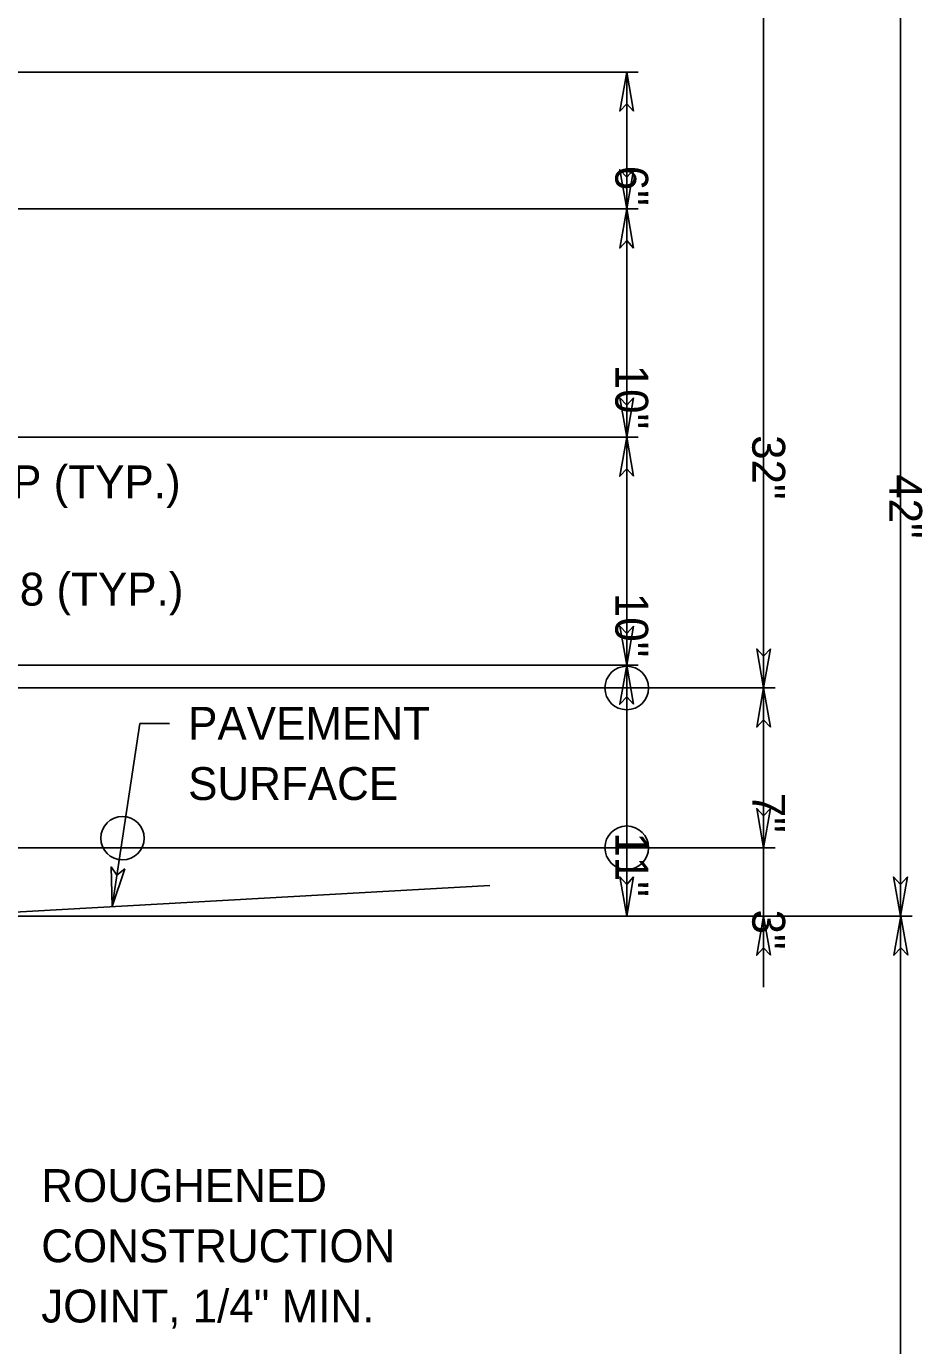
# Model space of a CAD drawing. Extents: x -26.5 to -19.2, y -3.6 to 6.6.
# Drawn here: x -22.083 to -20.447, y 2.961 to 5.371 of the extents above; entities that cross this region are included whole.
import ezdxf

# ---------------------------------------------------------------- set-up
doc = ezdxf.new("R2010")
doc.units = 0
for name, color, linetype in [('ANNO-WOUT', 7, 'Continuous'), ('DETL-DIMS', 7, 'Continuous'), ('Level 10', 7, 'Continuous'), ('Level 12', 7, 'Continuous'), ('SECT-GRND_P', 7, 'Continuous')]:
    doc.layers.add(name, color=color, linetype=linetype)

msp = doc.modelspace()

# ---------------------------------------------------------------- linework, layer by layer
at = {"layer": 'ANNO-WOUT'}
for centre in [(-20.987, 4.1622), (-21.9074, 3.8879), (-20.987, 3.8705)]:
    msp.add_circle(centre, 0.0397, dxfattribs=at)
at = {"layer": 'DETL-DIMS'}
for p, q in [((-20.987, 5.2872), (-20.9997, 5.2157)), ((-20.987, 5.2872), (-20.9745, 5.2157)), ((-20.987, 5.2292), (-20.9997, 5.2157)), ((-20.9745, 5.2157), (-20.987, 5.2292)), ((-20.987, 5.0372), (-20.9997, 5.1087)), ((-20.987, 5.0952), (-20.9997, 5.1087)), ((-20.987, 5.0372), (-20.9745, 5.1087)), ((-20.9745, 5.1087), (-20.987, 5.0952)), ((-20.987, 5.0372), (-20.9997, 4.9657)), ((-20.987, 5.0372), (-20.9745, 4.9657)), ((-20.987, 4.9792), (-20.9997, 4.9657)), ((-20.9745, 4.9657), (-20.987, 4.9792)), ((-20.987, 4.6205), (-20.9997, 4.692)), ((-20.987, 4.6785), (-20.9997, 4.692)), ((-20.987, 4.6205), (-20.9745, 4.692)), ((-20.9745, 4.692), (-20.987, 4.6785)), ((-20.987, 4.6205), (-20.9997, 4.549)), ((-20.987, 4.6205), (-20.9745, 4.549)), ((-20.987, 4.5625), (-20.9997, 4.549)), ((-20.9745, 4.549), (-20.987, 4.5625)), ((-20.987, 4.2039), (-20.9997, 4.2754)), ((-20.987, 4.2619), (-20.9997, 4.2754)), ((-20.987, 4.2039), (-20.9745, 4.2754)), ((-20.9745, 4.2754), (-20.987, 4.2619)), ((-20.737, 4.1622), (-20.7497, 4.2337)), ((-20.737, 4.2202), (-20.7497, 4.2337)), ((-20.737, 4.1622), (-20.7245, 4.2337)), ((-20.7245, 4.2337), (-20.737, 4.2202)), ((-20.987, 4.2039), (-20.9997, 4.1324)), ((-20.987, 4.2039), (-20.9745, 4.1324)), ((-20.987, 4.1459), (-20.9997, 4.1324)), ((-20.9745, 4.1324), (-20.987, 4.1459)), ((-20.737, 4.1622), (-20.7497, 4.0907)), ((-20.737, 4.1622), (-20.7245, 4.0907)), ((-20.737, 4.1042), (-20.7497, 4.0907)), ((-20.7245, 4.0907), (-20.737, 4.1042)), ((-20.737, 3.8705), (-20.7497, 3.942)), ((-20.737, 3.9285), (-20.7497, 3.942)), ((-20.737, 3.8705), (-20.7245, 3.942)), ((-20.7245, 3.942), (-20.737, 3.9285)), ((-21.9264, 3.7629), (-21.9282, 3.8355)), ((-21.9177, 3.8202), (-21.9282, 3.8355)), ((-21.9264, 3.7629), (-21.9033, 3.8317)), ((-21.9033, 3.8317), (-21.9177, 3.8202)), ((-20.987, 3.7455), (-20.9997, 3.817)), ((-20.987, 3.8035), (-20.9997, 3.817)), ((-20.987, 3.7455), (-20.9745, 3.817)), ((-20.9745, 3.817), (-20.987, 3.8035)), ((-20.487, 3.7455), (-20.4997, 3.817)), ((-20.487, 3.8035), (-20.4997, 3.817)), ((-20.487, 3.7455), (-20.4745, 3.817)), ((-20.4745, 3.817), (-20.487, 3.8035)), ((-20.737, 3.7455), (-20.7497, 3.674)), ((-20.737, 3.7455), (-20.7245, 3.674)), ((-20.4866, 3.7455), (-20.4993, 3.674)), ((-20.4866, 3.7455), (-20.4741, 3.674)), ((-20.737, 3.6875), (-20.7497, 3.674)), ((-20.7245, 3.674), (-20.737, 3.6875)), ((-20.4866, 3.6875), (-20.4993, 3.674)), ((-20.4741, 3.674), (-20.4866, 3.6875))]:
    msp.add_line(p, q, dxfattribs=at)
for points in [[(-20.9745, 5.2157), (-20.987, 5.2872), (-20.9997, 5.2157), (-20.987, 5.2292)], [(-20.9745, 5.1087), (-20.987, 5.0372), (-20.9997, 5.1087), (-20.987, 5.0952)], [(-20.9745, 4.9657), (-20.987, 5.0372), (-20.9997, 4.9657), (-20.987, 4.9792)], [(-20.9745, 4.692), (-20.987, 4.6205), (-20.9997, 4.692), (-20.987, 4.6785)], [(-20.9745, 4.549), (-20.987, 4.6205), (-20.9997, 4.549), (-20.987, 4.5625)], [(-20.9745, 4.2754), (-20.987, 4.2039), (-20.9997, 4.2754), (-20.987, 4.2619)], [(-20.7245, 4.2337), (-20.737, 4.1622), (-20.7497, 4.2337), (-20.737, 4.2202)], [(-20.9745, 4.1324), (-20.987, 4.2039), (-20.9997, 4.1324), (-20.987, 4.1459)], [(-20.7245, 4.0907), (-20.737, 4.1622), (-20.7497, 4.0907), (-20.737, 4.1042)], [(-20.7245, 3.942), (-20.737, 3.8705), (-20.7497, 3.942), (-20.737, 3.9285)], [(-21.9033, 3.8317), (-21.9264, 3.7629), (-21.9282, 3.8355), (-21.9177, 3.8202)], [(-20.9745, 3.817), (-20.987, 3.7455), (-20.9997, 3.817), (-20.987, 3.8035)], [(-20.4745, 3.817), (-20.487, 3.7455), (-20.4997, 3.817), (-20.487, 3.8035)], [(-20.7245, 3.674), (-20.737, 3.7455), (-20.7497, 3.674), (-20.737, 3.6875)], [(-20.4741, 3.674), (-20.4866, 3.7455), (-20.4993, 3.674), (-20.4866, 3.6875)]]:
    msp.add_lwpolyline(points, close=True, dxfattribs=at)
at = {"layer": 'Level 10'}
for p, q in [((-20.737, 4.1636), (-20.737, 5.4955)), ((-20.487, 5.4955), (-20.487, 3.7455)), ((-23.1151, 5.2872), (-20.9662, 5.2872)), ((-20.987, 5.0372), (-20.987, 5.2872)), ((-23.0877, 5.0372), (-20.9662, 5.0372)), ((-20.987, 4.6205), (-20.987, 5.0372)), ((-20.9662, 4.6205), (-23.0698, 4.6205)), ((-20.987, 4.2039), (-20.987, 4.6205)), ((-23.026, 4.2039), (-20.9662, 4.2039)), ((-20.987, 4.2039), (-20.987, 3.7455)), ((-22.8845, 4.1622), (-20.7162, 4.1622)), ((-20.737, 3.8705), (-20.737, 4.1636)), ((-21.8756, 4.0976), (-21.9264, 3.7629)), ((-21.8218, 4.0976), (-21.8756, 4.0976)), ((-22.6954, 3.8705), (-20.7162, 3.8705)), ((-20.737, 3.6159), (-20.737, 3.8705)), ((-22.1953, 3.7455), (-20.4662, 3.7455)), ((-22.0704, 3.7455), (-20.5912, 3.7455)), ((-20.487, 3.7455), (-20.487, 1.7452))]:
    msp.add_line(p, q, dxfattribs=at)
at = {"layer": 'SECT-GRND_P'}
msp.add_line((-22.237, 3.7455), (-21.237, 3.8014), dxfattribs=at)

# ---------------------------------------------------------------- texts
at = {"layer": 'Level 12'}
for s, p in [('6"', (-21.0078, 5.116)), ('10"', (-21.0078, 4.7527)), ('32"', (-20.7578, 4.624)), ('42"', (-20.5078, 4.5527)), ('10"', (-21.0078, 4.336)), ('7"', (-20.7578, 3.9709)), ('11"', (-21.0078, 3.8985)), ('3"', (-20.7578, 3.7575))]:
    msp.add_text(s, height=0.06001, rotation=270, dxfattribs=at).set_placement(p)
for s, p in [('2\'-2 1/2" LAP (TYP.)', (-22.5229, 4.5087)), ('SEE NOTE 8 (TYP.)', (-22.5229, 4.3127)), ('PAVEMENT ', (-21.7876, 4.0676)), ('SURFACE', (-21.7876, 3.9576)), ('ROUGHENED ', (-22.0557, 3.2234)), ('CONSTRUCTION ', (-22.0557, 3.1134)), ('JOINT, 1/4" MIN. ', (-22.0557, 3.0034))]:
    msp.add_text(s, height=0.06001, dxfattribs=at).set_placement(p)

doc.saveas('drawing.dxf')
